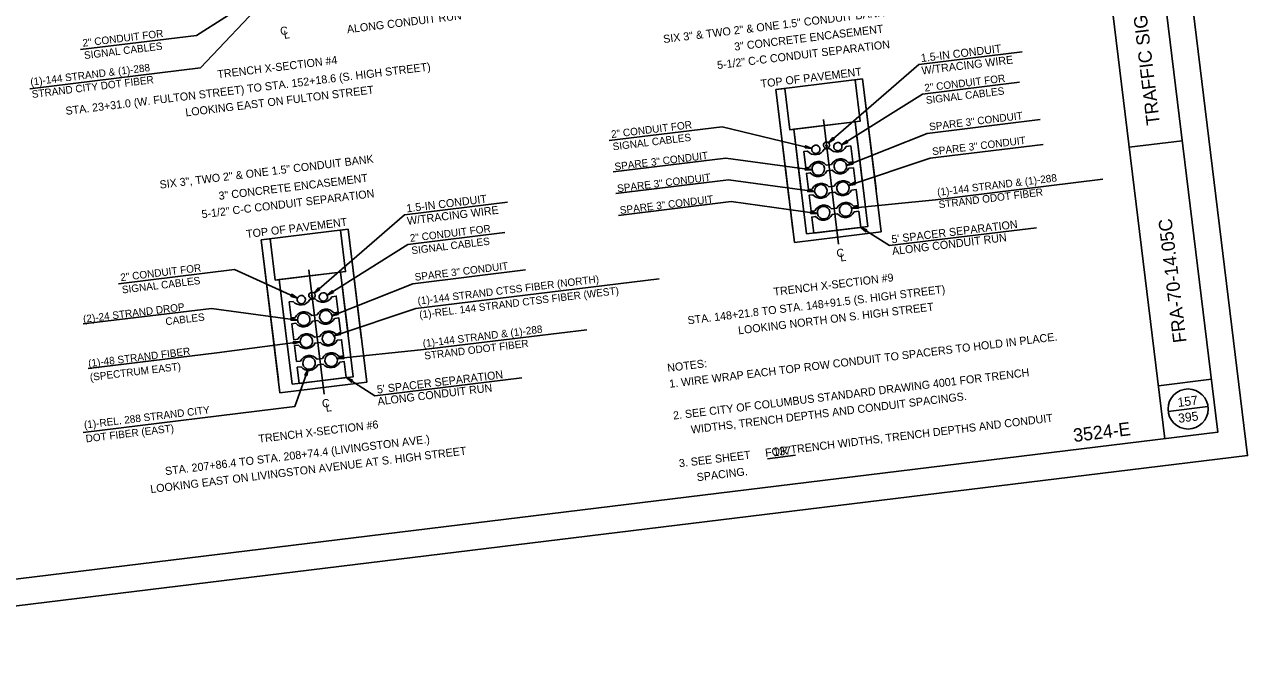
# Model space of a CAD drawing. Extents: x 91401 to 1830080, y 35587 to 712188.
# Drawn here: x 1828380 to 1829296, y 711096 to 711584 of the extents above; entities that cross this region are included whole.
import ezdxf

# ---------------------------------------------------------------- set-up
doc = ezdxf.new("R2010")
doc.units = 0
for name, color, linetype in [('Default', 7, 'Continuous'), ('SG_P_Text', 7, 'Continuous'), ('SH_Border', 7, 'Continuous'), ('SH_Cut_Line', 7, 'Continuous'), ('SH_Data', 7, 'Continuous'), ('SH_Text', 7, 'Continuous')]:
    doc.layers.add(name, color=color, linetype=linetype)

# ---------------------------------------------------------------- blocks, each defined once
blk = doc.blocks.new('POINT_DISPLAY')
at = {"layer": 'Default'}
blk.add_line((0, 0), (0, 0), dxfattribs=at)

msp = doc.modelspace()

# ---------------------------------------------------------------- linework, layer by layer
at = {"layer": 'SG_P_Text'}
msp.add_line((1828957.47, 711260.72), (1828936.41, 711258.15), dxfattribs=at)
at = {"layer": 'SH_Border'}
for p, q in [((1829234.27, 711273.16), (1829132.46, 712106.97)), ((1829207.6, 711491.54), (1829247.31, 711496.39)), ((1829229.42, 711312.87), (1829269.12, 711317.71))]:
    msp.add_line(p, q, dxfattribs=at)
msp.add_lwpolyline([(1827921.45, 711959.1), (1829172.16, 712111.82), (1829273.97, 711278.01), (1828023.26, 711125.29)], close=True, dxfattribs=at)
at = {"layer": 'SH_Cut_Line'}
msp.add_lwpolyline([(1827946.27, 711095.75), (1829296.25, 711260.58), (1829189.59, 712134.09), (1827839.62, 711969.26)], close=True, dxfattribs=at)
at = {"layer": 'SH_Data'}
msp.add_line((1829236.8, 711293.62), (1829266.58, 711297.25), dxfattribs=at)
msp.add_circle((1829251.69, 711295.44), 15, dxfattribs=at)
at = {"layer": 'SH_Text'}
for p, q in [((1828551.05, 711602.46), (1828508.67, 711575.26)), ((1828565.33, 711608.18), (1828511.64, 711550.98)), ((1828421.77, 711564.64), (1828508.67, 711575.26)), ((1829049.94, 711553.58), (1829127.31, 711563.02)), ((1828982.27, 711494.9), (1829049.94, 711553.58)), ((1828383.61, 711535.34), (1828511.64, 711550.98)), ((1828949.43, 711535.56), (1828942.72, 711534.74)), ((1828953.21, 711504.6), (1828949.43, 711535.56)), ((1829007.75, 711542.68), (1829002.16, 711542)), ((1829005.94, 711511.04), (1829002.16, 711542)), ((1829021.74, 711428.08), (1829007.75, 711542.68)), ((1829052.66, 711531.31), (1829125.35, 711540.18)), ((1828942.72, 711534.74), (1828956.71, 711420.15)), ((1828992.07, 711493.29), (1829052.66, 711531.31)), ((1828978.38, 711512.26), (1828989.76, 711419.02)), ((1829002.1, 711510.57), (1829011.67, 711432.18)), ((1829056.26, 711501.88), (1829140.79, 711512.2)), ((1828902.43, 711506.86), (1828817.9, 711496.54)), ((1828969.67, 711490.7), (1828902.43, 711506.86)), ((1828956.19, 711504.96), (1828953.21, 711504.6)), ((1828965.76, 711426.57), (1828956.19, 711504.96)), ((1828995.73, 711477.77), (1829056.26, 711501.88)), ((1829003.25, 711501.15), (1829005.1, 711486.01)), ((1829004.08, 711494.3), (1829006.61, 711473.66)), ((1829058.51, 711483.39), (1829143.05, 711493.71)), ((1828905.29, 711483.44), (1828820.76, 711473.12)), ((1828969.84, 711474.61), (1828905.29, 711483.44)), ((1828997.28, 711462.93), (1829058.51, 711483.39)), ((1828907.28, 711467.11), (1828822.75, 711456.79)), ((1828971.84, 711458.28), (1828907.28, 711467.11)), ((1828971.84, 711458.28), (1828907.28, 711467.11)), ((1829062.32, 711452.25), (1829187.82, 711467.57)), ((1828664.36, 711440.98), (1828741.73, 711450.42)), ((1828909.28, 711450.78), (1828824.75, 711440.46)), ((1828973.83, 711441.95), (1828909.28, 711450.78)), ((1828999.55, 711445.9), (1829062.32, 711452.25)), ((1828596.69, 711382.3), (1828664.36, 711440.98)), ((1828622.17, 711430.08), (1828616.58, 711429.4)), ((1828620.36, 711398.44), (1828616.58, 711429.4)), ((1828636.16, 711315.49), (1828622.17, 711430.08)), ((1828667.08, 711418.71), (1828739.77, 711427.58)), ((1828956.71, 711420.15), (1829021.74, 711428.08)), ((1829011.67, 711432.18), (1828965.76, 711426.57)), ((1829006.37, 711431.53), (1829027.86, 711417.81)), ((1829027.86, 711417.81), (1829138.07, 711431.27)), ((1828563.85, 711422.96), (1828557.14, 711422.14)), ((1828557.14, 711422.14), (1828571.13, 711307.55)), ((1828567.63, 711392), (1828563.85, 711422.96)), ((1828606.49, 711380.69), (1828667.08, 711418.71)), ((1828450.12, 711389.28), (1828537.02, 711399.89)), ((1828584.22, 711378.52), (1828537.02, 711399.89)), ((1828592.8, 711399.66), (1828604.18, 711306.42)), ((1828616.52, 711397.97), (1828626.09, 711319.58)), ((1828670.68, 711389.28), (1828755.21, 711399.6)), ((1828570.61, 711392.36), (1828567.63, 711392)), ((1828580.18, 711313.97), (1828570.61, 711392.36)), ((1828610.15, 711365.17), (1828670.68, 711389.28)), ((1828617.67, 711388.55), (1828619.52, 711373.41)), ((1828672.93, 711370.79), (1828855.36, 711393.06)), ((1828618.5, 711381.7), (1828621.02, 711361.06)), ((1828519.71, 711370.84), (1828423.7, 711359.12)), ((1828584.26, 711362.01), (1828519.71, 711370.84)), ((1828611.7, 711350.33), (1828672.93, 711370.79)), ((1828676.74, 711339.65), (1828801.03, 711354.83)), ((1828586.25, 711345.68), (1828523.77, 711337.6)), ((1828523.77, 711337.6), (1828427.4, 711325.83)), ((1828613.97, 711333.3), (1828676.74, 711339.65)), ((1828592.26, 711325.26), (1828582.15, 711297.18)), ((1828571.13, 711307.55), (1828636.16, 711315.49)), ((1828626.09, 711319.58), (1828580.18, 711313.97)), ((1828620.79, 711318.93), (1828642.28, 711305.21)), ((1828642.28, 711305.21), (1828752.48, 711318.67)), ((1828423.69, 711277.83), (1828582.15, 711297.18))]:
    msp.add_line(p, q, dxfattribs=at)
for points in [[(1828942.72, 711534.74), (1828995.45, 711541.18), (1829007.75, 711542.68), (1829007.75, 711542.68)], [(1828949.43, 711535.56), (1828953.21, 711504.6), (1829005.94, 711511.04), (1829002.16, 711542)], [(1829002.16, 711542), (1829005.94, 711511.04), (1829002.1, 711510.57)], [(1829017.82, 711460.16), (1829007.75, 711542.68)], [(1828952.8, 711452.22), (1828942.72, 711534.74)], [(1828956.19, 711504.96), (1828978.94, 711507.74), (1829002.1, 711510.57), (1829007.75, 711464.25)], [(1828961.84, 711458.64), (1828956.19, 711504.96)], [(1828983.08, 711490.64), (1828979.02, 711490.14)], [(1828997, 711480.12), (1829000.39, 711480.53), (1828998.92, 711492.57), (1828995.53, 711492.16)], [(1828966.57, 711488.62), (1828963.65, 711488.26), (1828965.12, 711476.23)], [(1828955.56, 711429.55), (1828949.91, 711475.87)], [(1828965.12, 711476.23), (1828968.04, 711476.58)], [(1828968.57, 711472.28), (1828965.64, 711471.93), (1828967.11, 711459.89)], [(1828980.49, 711478.1), (1828984.55, 711478.6)], [(1828985.07, 711474.3), (1828981.02, 711473.8)], [(1828998.99, 711463.78), (1829002.38, 711464.19), (1829000.91, 711476.23), (1828997.52, 711475.82)], [(1828982.49, 711461.77), (1828986.54, 711462.26)], [(1828967.11, 711459.89), (1828970.04, 711460.24)], [(1828970.56, 711455.95), (1828967.64, 711455.59), (1828969.11, 711443.56)], [(1828987.07, 711457.97), (1828983.01, 711457.47)], [(1829000.99, 711447.45), (1829004.37, 711447.86), (1829002.9, 711459.9), (1828999.52, 711459.49)], [(1828969.11, 711443.56), (1828972.03, 711443.91)], [(1828971.1, 711427.23), (1829006.37, 711431.53), (1829004.9, 711443.57), (1829001.51, 711443.16)], [(1828984.48, 711445.43), (1828988.54, 711445.93)], [(1828972.56, 711439.62), (1828969.63, 711439.26), (1828971.1, 711427.23)], [(1828989.06, 711441.64), (1828985.01, 711441.14)], [(1828557.14, 711422.14), (1828609.87, 711428.58), (1828622.17, 711430.08), (1828622.17, 711430.08)], [(1828563.85, 711422.96), (1828567.63, 711392), (1828620.36, 711398.44), (1828616.58, 711429.4)], [(1828616.58, 711429.4), (1828620.36, 711398.44), (1828616.52, 711397.97)], [(1828632.24, 711347.56), (1828622.17, 711430.08)], [(1828567.22, 711339.62), (1828557.14, 711422.14)], [(1828570.61, 711392.36), (1828593.36, 711395.14), (1828616.52, 711397.97), (1828622.17, 711351.65)], [(1828576.26, 711346.05), (1828570.61, 711392.36)], [(1828611.42, 711367.52), (1828614.8, 711367.93), (1828613.33, 711379.97), (1828609.95, 711379.56)], [(1828580.99, 711376.02), (1828578.07, 711375.67), (1828579.54, 711363.63)], [(1828597.5, 711378.04), (1828593.44, 711377.54)], [(1828569.98, 711316.95), (1828564.33, 711363.27)], [(1828579.54, 711363.63), (1828582.46, 711363.99)], [(1828594.91, 711365.51), (1828598.97, 711366)], [(1828599.49, 711361.7), (1828595.44, 711361.2)], [(1828613.41, 711351.18), (1828616.8, 711351.6), (1828615.33, 711363.63), (1828611.94, 711363.22)], [(1828582.99, 711359.68), (1828580.06, 711359.33), (1828581.53, 711347.29)], [(1828581.53, 711347.29), (1828584.46, 711347.65)], [(1828584.98, 711343.35), (1828582.06, 711343), (1828583.53, 711330.96)], [(1828596.91, 711349.17), (1828600.96, 711349.66)], [(1828601.48, 711345.37), (1828597.43, 711344.87)], [(1828615.41, 711334.85), (1828618.79, 711335.26), (1828617.32, 711347.3), (1828613.94, 711346.89)], [(1828598.9, 711332.84), (1828602.95, 711333.33)], [(1828583.53, 711330.96), (1828586.45, 711331.31)], [(1828586.97, 711327.02), (1828584.05, 711326.66), (1828585.52, 711314.63)], [(1828585.52, 711314.63), (1828620.79, 711318.93), (1828619.32, 711330.97), (1828615.93, 711330.56)], [(1828603.48, 711329.04), (1828599.43, 711328.54)]]:
    msp.add_lwpolyline(points, dxfattribs=at)
for points in [[(1828965.76, 711426.57), (1829011.67, 711432.18), (1829002.1, 711510.57), (1828956.19, 711504.96)], [(1828986.61, 711497.51), (1828985.53, 711498.78), (1828982.27, 711494.9)], [(1828964.61, 711491.06), (1828965, 711492.68), (1828969.67, 711490.7)], [(1828996.76, 711495.2), (1828995.89, 711496.62), (1828992.07, 711493.29)], [(1829000.68, 711478.85), (1829000.06, 711480.4), (1828995.73, 711477.77)], [(1828964.77, 711474.46), (1828965, 711476.11), (1828969.84, 711474.61)], [(1829002.28, 711463.73), (1829001.76, 711465.31), (1828997.28, 711462.93)], [(1828966.77, 711458.13), (1828966.99, 711459.78), (1828971.84, 711458.28)], [(1828968.76, 711441.8), (1828968.99, 711443.45), (1828973.83, 711441.95)], [(1829004.61, 711445.58), (1829004.43, 711447.24), (1828999.55, 711445.9)], [(1829011.03, 711429.54), (1829010.13, 711428.13), (1829006.37, 711431.53)], [(1828580.18, 711313.97), (1828626.09, 711319.58), (1828616.52, 711397.97), (1828570.61, 711392.36)], [(1828579.32, 711379.83), (1828580.01, 711381.34), (1828584.22, 711378.52)], [(1828601.03, 711384.91), (1828599.95, 711386.18), (1828596.69, 711382.3)], [(1828611.18, 711382.6), (1828610.3, 711384.02), (1828606.49, 711380.69)], [(1828579.19, 711361.86), (1828579.42, 711363.52), (1828584.26, 711362.01)], [(1828615.1, 711366.25), (1828614.48, 711367.8), (1828610.15, 711365.17)], [(1828616.7, 711351.13), (1828616.18, 711352.71), (1828611.7, 711350.33)], [(1828581.39, 711344.25), (1828581.19, 711345.91), (1828586.25, 711345.68)], [(1828619.02, 711332.98), (1828618.85, 711334.64), (1828613.97, 711333.3)], [(1828591.35, 711320.27), (1828589.79, 711320.84), (1828592.26, 711325.26)], [(1828625.45, 711316.94), (1828624.55, 711315.53), (1828620.79, 711318.93)]]:
    msp.add_lwpolyline(points, close=True, dxfattribs=at)
for centre, radius, start, end in [((1828972.31, 711493.38), 7.45, 219.64855, 334.27431), ((1828972.71, 711489.97), 3.13, 6.96143, 186.96143), ((1828972.71, 711489.97), 3.13, 186.96143, 6.96143), ((1828980.72, 711493.13), 2.35, 6.96143, 186.96143), ((1828980.72, 711493.13), 2.35, 186.96143, 6.96143), ((1828980.7, 711492.72), 0.5, 6.96143, 186.96143), ((1828980.7, 711492.72), 0.5, 186.96143, 6.96143), ((1828988.81, 711495.39), 7.45, 219.64855, 334.27431), ((1828989.22, 711491.98), 3.13, 6.96143, 186.96143), ((1828989.22, 711491.98), 3.13, 186.96143, 6.96143), ((1828974.76, 711473.35), 7.45, 39.64855, 154.27431), ((1828991.26, 711475.36), 7.45, 39.64855, 154.27431), ((1828991.06, 711477.2), 4.7, 6.96143, 186.96143), ((1828974.31, 711477.04), 7.45, 219.64855, 334.27431), ((1828974.52, 711475.18), 4.7, 6.96143, 186.96143), ((1828974.52, 711475.18), 4.7, 186.96143, 6.96143), ((1828990.81, 711479.05), 7.45, 219.64855, 334.27431), ((1828991.06, 711477.2), 4.7, 186.96143, 6.96143), ((1828976.75, 711457.01), 7.45, 39.64855, 154.27431), ((1828976.51, 711458.85), 4.7, 6.96143, 186.96143), ((1828993.25, 711459.03), 7.45, 39.64855, 154.27431), ((1828993.05, 711460.87), 4.7, 6.96143, 186.96143), ((1828976.3, 711460.71), 7.45, 219.64855, 334.27431), ((1828976.51, 711458.85), 4.7, 186.96143, 6.96143), ((1828992.8, 711462.72), 7.45, 219.64855, 334.27431), ((1828993.05, 711460.87), 4.7, 186.96143, 6.96143), ((1828978.74, 711440.68), 7.45, 39.64855, 154.27431), ((1828978.51, 711442.51), 4.7, 6.96143, 186.96143), ((1828995.25, 711442.69), 7.45, 39.64855, 154.27431), ((1828995.05, 711444.53), 4.7, 6.96143, 186.96143), ((1828995.05, 711444.53), 4.7, 186.96143, 6.96143), ((1828978.29, 711444.37), 7.45, 219.64855, 334.27431), ((1828978.51, 711442.51), 4.7, 186.96143, 6.96143), ((1828994.8, 711446.39), 7.45, 219.64855, 334.27431), ((1828587.13, 711377.37), 3.13, 6.96143, 186.96143), ((1828595.14, 711380.53), 2.35, 6.96143, 186.96143), ((1828595.14, 711380.53), 2.35, 186.96143, 6.96143), ((1828595.12, 711380.12), 0.5, 6.96143, 186.96143), ((1828595.12, 711380.12), 0.5, 186.96143, 6.96143), ((1828603.23, 711382.79), 7.45, 219.64855, 334.27431), ((1828603.64, 711379.38), 3.13, 6.96143, 186.96143), ((1828603.64, 711379.38), 3.13, 186.96143, 6.96143), ((1828586.73, 711380.78), 7.45, 219.64855, 334.27431), ((1828587.13, 711377.37), 3.13, 186.96143, 6.96143), ((1828605.68, 711362.77), 7.45, 39.64855, 154.27431), ((1828589.17, 711360.75), 7.45, 39.64855, 154.27431), ((1828588.72, 711364.44), 7.45, 219.64855, 334.27431), ((1828588.94, 711362.58), 4.7, 6.96143, 186.96143), ((1828588.94, 711362.58), 4.7, 186.96143, 6.96143), ((1828605.23, 711366.45), 7.45, 219.64855, 334.27431), ((1828605.48, 711364.6), 4.7, 6.96143, 186.96143), ((1828605.48, 711364.6), 4.7, 186.96143, 6.96143), ((1828591.17, 711344.41), 7.45, 39.64855, 154.27431), ((1828607.67, 711346.43), 7.45, 39.64855, 154.27431), ((1828607.47, 711348.27), 4.7, 6.96143, 186.96143), ((1828590.72, 711348.11), 7.45, 219.64855, 334.27431), ((1828590.93, 711346.25), 4.7, 6.96143, 186.96143), ((1828590.93, 711346.25), 4.7, 186.96143, 6.96143), ((1828607.22, 711350.12), 7.45, 219.64855, 334.27431), ((1828607.47, 711348.27), 4.7, 186.96143, 6.96143), ((1828593.16, 711328.08), 7.45, 39.64855, 154.27431), ((1828592.93, 711329.91), 4.7, 6.96143, 186.96143), ((1828609.67, 711330.1), 7.45, 39.64855, 154.27431), ((1828609.47, 711331.93), 4.7, 6.96143, 186.96143), ((1828592.71, 711331.78), 7.45, 219.64855, 334.27431), ((1828592.93, 711329.91), 4.7, 186.96143, 6.96143), ((1828609.22, 711333.79), 7.45, 219.64855, 334.27431), ((1828609.47, 711331.93), 4.7, 186.96143, 6.96143)]:
    msp.add_arc(centre, radius, start, end, dxfattribs=at)

# ---------------------------------------------------------------- block references
at = {"layer": 'SH_Text', "xscale": 1.5748, "yscale": 1.5748000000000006, "rotation": 6.96142799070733}
for p in [(1828989.05, 711423.7), (1828603.47, 711311.1)]:
    msp.add_blockref('POINT_DISPLAY', p, dxfattribs=at)

# ---------------------------------------------------------------- texts
at = {"layer": 'SG_P_Text'}
for s, height, rotation, p in [('3524-E', 10, 6.96458, (1829166.2, 711270.64)), ('137', 6, 6.96143, (1828941.15, 711259.91))]:
    msp.add_text(s, height=height, rotation=rotation, dxfattribs=at).set_placement(p)
at = {"layer": 'SH_Data'}
for s, p in [('TRAFFIC SIGNAL INTERCONNECT TRENCH TYPICAL SECTIONS', (1829230.69, 711508.69)), ('FRA-70-14.05C', (1829250.6, 711345.65))]:
    msp.add_text(s, height=10, rotation=96.96143, dxfattribs=at).set_placement(p)
at = {"layer": 'SH_Text'}
for s, height, p in [('ALONG CONDUIT RUN', 6, (1828621.67, 711576.93)), ('SIX 3" & TWO 2" & ONE 1.5" CONDUIT BANK', 6, (1828858.69, 711569.54)), ('C', 6, (1828571.63, 711575.5)), ('3" CONCRETE ENCASEMENT', 6, (1828911.94, 711563.85)), ('2" CONDUIT FOR ', 5.6, (1828423.51, 711566.82)), ('L', 6, (1828574.33, 711572.71)), ('5-1/2" C-C CONDUIT SEPARATION', 6, (1828899.12, 711550.08)), ('SIGNAL CABLES', 5.6, (1828424.65, 711557.55)), ('1.5-IN CONDUIT', 6, (1829051.82, 711555.33)), ('(1)-144 STRAND & (1)-288 ', 5.6, (1828384.39, 711537.68)), ('STA. 23+31.0 (W. FULTON STREET) TO STA. 152+18.6 (S. HIGH STREET)', 6, (1828410.81, 711515.72)), ('TRENCH X-SECTION #4', 6, (1828524.61, 711543.14)), ('W/TRACING WIRE', 6, (1829052.33, 711545.98)), ('STRAND CITY DOT FIBER', 5.6, (1828385.52, 711528.42)), ('TOP OF PAVEMENT', 6, (1828931.75, 711536.1)), ('2" CONDUIT FOR ', 5.6, (1829054.44, 711533.21)), ('LOOKING EAST ON FULTON STREET', 6, (1828500.61, 711514.6)), ('SIGNAL CABLES', 5.6, (1829055.57, 711523.95)), ('SPARE 3" CONDUIT', 5.6, (1829058, 711504.05)), ('2" CONDUIT FOR ', 5.6, (1828819.67, 711498.44)), ('SIGNAL CABLES', 5.6, (1828820.8, 711489.18)), ('SPARE 3" CONDUIT', 5.6, (1829060.26, 711485.56)), ('SIX 3", TWO 2" & ONE 1.5" CONDUIT BANK', 6, (1828481.31, 711460.49)), ('SPARE 3" CONDUIT', 5.6, (1828822.21, 711474.18)), ('3" CONCRETE ENCASEMENT', 6, (1828525.57, 711452.09)), ('SPARE 3" CONDUIT', 5.6, (1828824.2, 711457.85)), ('(1)-144 STRAND & (1)-288 ', 5.6, (1829063.98, 711455.06)), ('5-1/2" C-C CONDUIT SEPARATION', 6, (1828512.75, 711438.33)), ('1.5-IN CONDUIT', 6, (1828666.24, 711442.73)), ('SPARE 3" CONDUIT', 5.6, (1828826.19, 711441.52)), ('STRAND ODOT FIBER', 5.6, (1829065.11, 711445.79)), ('W/TRACING WIRE', 6, (1828666.74, 711433.38)), ('TOP OF PAVEMENT', 6, (1828546.17, 711423.5)), ("5' SPACER SEPARATION", 6, (1829029.74, 711419.56)), ('2" CONDUIT FOR ', 5.6, (1828668.86, 711420.61)), ('ALONG CONDUIT RUN', 6, (1829030.19, 711410.69)), ('SIGNAL CABLES', 5.6, (1828669.99, 711411.35)), ('C', 6, (1828988.56, 711409.09)), ('L', 6, (1828991.3, 711405.9)), ('2" CONDUIT FOR ', 5.6, (1828451.9, 711391.18)), ('SPARE 3" CONDUIT', 5.6, (1828672.42, 711391.45)), ('SIGNAL CABLES', 5.6, (1828453.03, 711381.92)), ('(1)-144 STRAND CTSS FIBER (NORTH)', 5.6, (1828674.6, 711373.59)), ('STA. 148+21.8 TO STA. 148+91.5 (S. HIGH STREET)', 6, (1828876.95, 711358.82)), ('TRENCH X-SECTION #9', 6, (1828941.4, 711380.22)), ('(1)-REL. 144 STRAND CTSS FIBER (WEST)', 5.6, (1828675.86, 711363.27)), ('(2)-24 STRAND DROP', 5.6, (1828423.92, 711360.03)), ('LOOKING NORTH ON S. HIGH STREET', 6, (1828914.85, 711351.35)), (' CABLES', 5.6, (1828483.55, 711357.91)), ('(1)-144 STRAND & (1)-288 ', 5.6, (1828678.49, 711341.7)), ('1. WIRE WRAP EACH TOP ROW CONDUIT TO SPACERS TO HOLD IN PLACE.', 6, (1828863.22, 711311.3)), ('STRAND ODOT FIBER ', 5.6, (1828679.62, 711332.44)), ('(1)-48 STRAND FIBER ', 5.6, (1828427.76, 711326.76)), ('(SPECTRUM EAST)', 5.6, (1828429.02, 711316.44)), ("5' SPACER SEPARATION", 6, (1828644.16, 711306.97)), ('NOTES:', 6, (1828861.76, 711323.21)), ('2. SEE CITY OF COLUMBUS STANDARD DRAWING 4001 FOR TRENCH ', 6, (1828866.13, 711287.48)), ('ALONG CONDUIT RUN', 6, (1828644.61, 711298.09)), ('WIDTHS, TRENCH DEPTHS AND CONDUIT SPACINGS.', 6, (1828879.49, 711277.02)), ('(1)-REL. 288 STRAND CITY ', 5.6, (1828424.61, 711280.72)), ('C', 6, (1828602.98, 711296.49)), ('L', 6, (1828605.72, 711293.31)), ('157', 6.8, (1829244.27, 711296.93)), ('3. SEE SHEET     FOR TRENCH WIDTHS, TRENCH DEPTHS AND CONDUIT ', 6, (1828870.49, 711251.74)), ('395', 6.8, (1829244.68, 711285.06)), ('DOT FIBER (EAST)', 5.6, (1828425.87, 711270.39)), ('TRENCH X-SECTION #6', 6, (1828555.37, 711270.09)), ('STA. 207+86.4 TO STA. 208+74.4 (LIVINGSTON AVE.)', 6, (1828485.37, 711245.86)), ('LOOKING EAST ON LIVINGSTON AVENUE AT S. HIGH STREET', 6, (1828474.34, 711232.42)), ('SPACING.', 6, (1828883.85, 711241.29))]:
    msp.add_text(s, height=height, rotation=6.96143, dxfattribs=at).set_placement(p)

doc.saveas('drawing.dxf')
